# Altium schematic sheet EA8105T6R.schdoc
size 127 x 101 mm
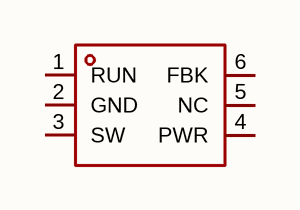
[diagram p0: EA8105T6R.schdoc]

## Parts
U?  ea8105t6r  [SOT-23-6_L2.9-W1.6-P0.95-LS2.9-BL]  (value not drawn)

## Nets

Not connected (* = marked no-connect by the designer): U? 1(RUN) 2(GND) 3(SW) 4(PWR) 5(NC) 6(FBK)

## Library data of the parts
U? = ea8105t6r: 功能类型:降压型;工作电压:2.7V~5.5V;输出电压:600mV~5.5V;输出电流:2A;输出类型:可调;; Manufacturer: everanalog(申风); AddInBom: yes; ModelId: 7835d1ec76e347009cd4512957858e4e; ModelTransform: 114.173,114.173,0,0,0,0,0,0,0; Function: 降压型; Output Current: 2A; Frequency - Switching: 1.5MHz; Synchronous Rectifier: 是; Number of Outputs: 1; Topology: 降压式; Quiescent Current: 40uA; Switch tube (built-in/external): 内置; Output Type: 可调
